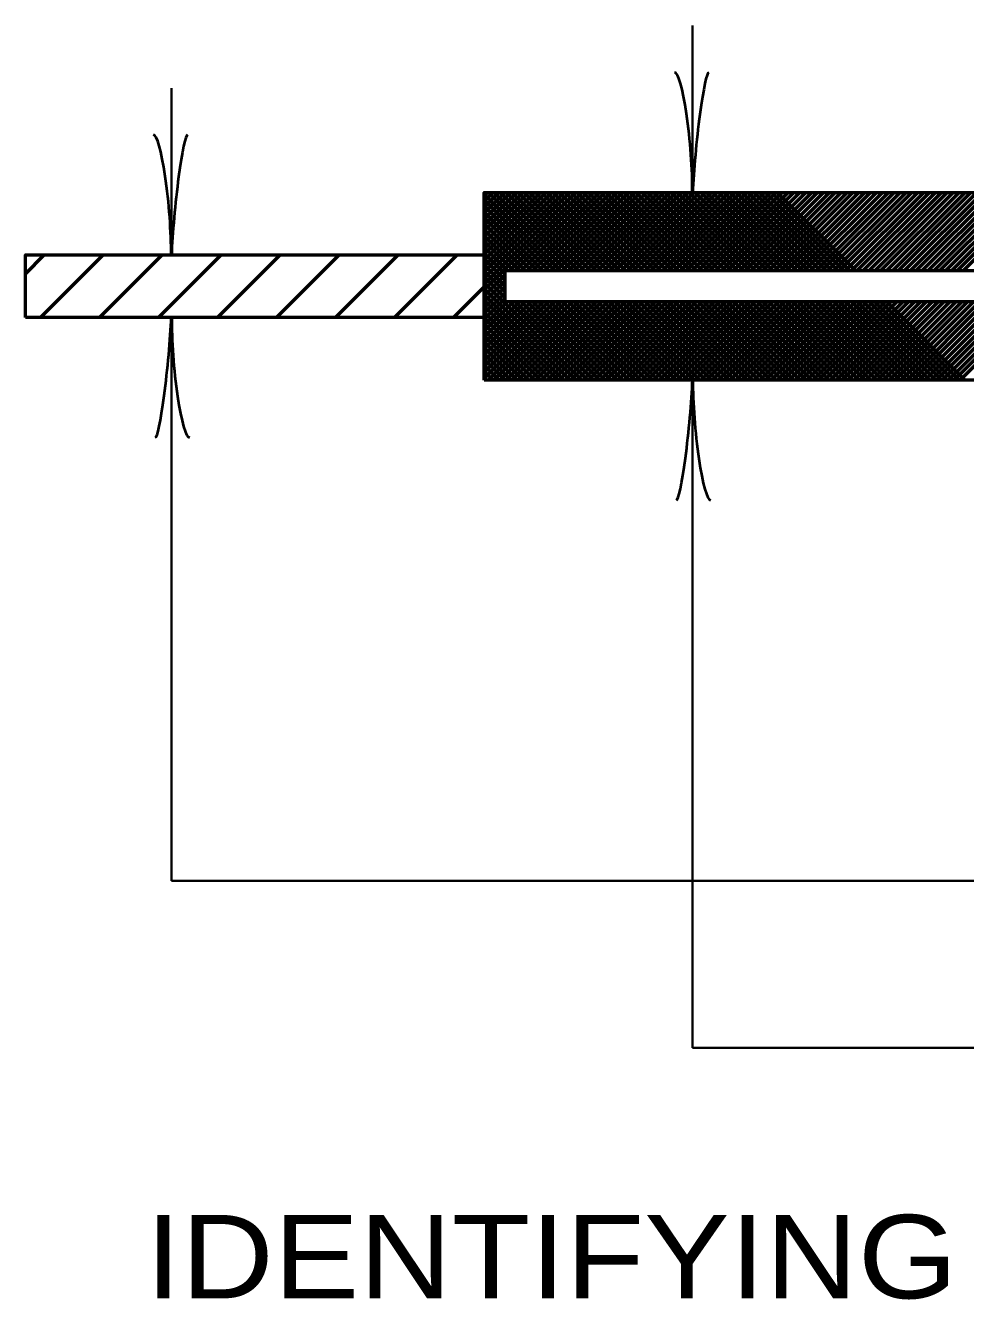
# Model space of a CAD drawing. Extents: x -32 to 824, y -6 to 538.
# Drawn here: x 339.48 to 366.53, y 145.51 to 182.16 of the extents above; entities that cross this region are included whole.
import ezdxf

# ---------------------------------------------------------------- set-up
doc = ezdxf.new("R2010")
doc.units = 0
doc.header["$LTSCALE"] = 1.1
doc.layers.add('1', color=7, linetype='Continuous', lineweight=53)

msp = doc.modelspace()

# ---------------------------------------------------------------- linework, layer by layer
at = {"layer": '1', "lineweight": 35}
for p, q in [((358.679, 177.362), (358.679, 182.162)), ((343.679, 175.562), (343.679, 180.362)), ((343.679, 173.762), (343.679, 157.562)), ((358.679, 171.962), (358.679, 152.752)), ((343.679, 157.562), (407.879, 157.562)), ((358.679, 152.752), (394.762, 152.752))]:
    msp.add_line(p, q, dxfattribs=at)
at = {"layer": '1'}
for p, q in [((352.679, 171.962), (352.679, 177.362)), ((352.679, 177.27), (352.771, 177.362)), ((352.679, 177.1), (352.94, 177.362)), ((352.679, 176.93), (353.11, 177.362)), ((352.679, 176.761), (353.28, 177.362)), ((352.679, 176.591), (353.45, 177.362)), ((352.679, 176.421), (353.619, 177.362)), ((352.679, 176.252), (353.789, 177.362)), ((352.679, 176.082), (353.959, 177.362)), ((352.679, 175.912), (354.128, 177.362)), ((352.679, 175.742), (354.298, 177.362)), ((352.679, 175.573), (354.468, 177.362)), ((352.679, 175.403), (354.637, 177.362)), ((352.679, 175.233), (354.807, 177.362)), ((352.679, 175.064), (354.977, 177.362)), ((352.679, 174.894), (355.147, 177.362)), ((352.679, 174.724), (355.316, 177.362)), ((352.679, 174.555), (355.486, 177.362)), ((354.88, 175.112), (352.679, 177.313)), ((354.711, 175.112), (352.679, 177.143)), ((355.05, 175.112), (352.8, 177.362)), ((355.22, 175.112), (352.97, 177.362)), ((355.389, 175.112), (353.139, 177.362)), ((355.559, 175.112), (353.309, 177.362)), ((353.406, 175.112), (355.656, 177.362)), ((355.729, 175.112), (353.479, 177.362)), ((353.575, 175.112), (355.825, 177.362)), ((355.899, 175.112), (353.649, 177.362)), ((353.745, 175.112), (355.995, 177.362)), ((356.068, 175.112), (353.818, 177.362)), ((353.915, 175.112), (356.165, 177.362)), ((356.238, 175.112), (353.988, 177.362)), ((354.084, 175.112), (356.334, 177.362)), ((356.408, 175.112), (354.158, 177.362)), ((354.254, 175.112), (356.504, 177.362)), ((356.577, 175.112), (354.327, 177.362)), ((354.424, 175.112), (356.674, 177.362)), ((356.747, 175.112), (354.497, 177.362)), ((354.594, 175.112), (356.844, 177.362)), ((356.917, 175.112), (354.667, 177.362)), ((354.763, 175.112), (357.013, 177.362)), ((357.087, 175.112), (354.837, 177.362)), ((354.933, 175.112), (357.183, 177.362)), ((357.256, 175.112), (355.006, 177.362)), ((355.103, 175.112), (357.353, 177.362)), ((357.426, 175.112), (355.176, 177.362)), ((355.273, 175.112), (357.523, 177.362)), ((357.596, 175.112), (355.346, 177.362)), ((355.442, 175.112), (357.692, 177.362)), ((357.765, 175.112), (355.515, 177.362)), ((355.612, 175.112), (357.862, 177.362)), ((357.935, 175.112), (355.685, 177.362)), ((355.782, 175.112), (358.032, 177.362)), ((358.105, 175.112), (355.855, 177.362)), ((355.951, 175.112), (358.201, 177.362)), ((358.274, 175.112), (356.024, 177.362)), ((356.121, 175.112), (358.371, 177.362)), ((358.444, 175.112), (356.194, 177.362)), ((356.291, 175.112), (358.541, 177.362)), ((358.614, 175.112), (356.364, 177.362)), ((356.46, 175.112), (358.71, 177.362)), ((358.784, 175.112), (356.534, 177.362)), ((356.63, 175.112), (358.88, 177.362)), ((358.953, 175.112), (356.703, 177.362)), ((356.8, 175.112), (359.05, 177.362)), ((359.123, 175.112), (356.873, 177.362)), ((356.97, 175.112), (359.22, 177.362)), ((359.293, 175.112), (357.043, 177.362)), ((357.139, 175.112), (359.389, 177.362)), ((359.462, 175.112), (357.212, 177.362)), ((357.309, 175.112), (359.559, 177.362)), ((359.632, 175.112), (357.382, 177.362)), ((357.479, 175.112), (359.729, 177.362)), ((359.802, 175.112), (357.552, 177.362)), ((357.648, 175.112), (359.898, 177.362)), ((359.971, 175.112), (357.721, 177.362)), ((357.818, 175.112), (360.068, 177.362)), ((360.141, 175.112), (357.891, 177.362)), ((357.988, 175.112), (360.238, 177.362)), ((360.311, 175.112), (358.061, 177.362)), ((358.158, 175.112), (360.408, 177.362)), ((360.481, 175.112), (358.231, 177.362)), ((358.327, 175.112), (360.577, 177.362)), ((360.65, 175.112), (358.4, 177.362)), ((358.497, 175.112), (360.747, 177.362)), ((360.82, 175.112), (358.57, 177.362)), ((358.667, 175.112), (360.917, 177.362)), ((360.99, 175.112), (358.74, 177.362)), ((358.836, 175.112), (361.086, 177.362)), ((361.16, 175.112), (358.91, 177.362)), ((359.006, 175.112), (361.256, 177.362)), ((361.329, 175.112), (359.079, 177.362)), ((359.176, 175.112), (361.426, 177.362)), ((361.499, 175.112), (359.249, 177.362)), ((359.345, 175.112), (361.595, 177.362)), ((361.669, 175.112), (359.419, 177.362)), ((359.515, 175.112), (361.765, 177.362)), ((361.838, 175.112), (359.588, 177.362)), ((359.685, 175.112), (361.935, 177.362)), ((362.008, 175.112), (359.758, 177.362)), ((359.855, 175.112), (362.105, 177.362)), ((362.178, 175.112), (359.928, 177.362)), ((360.024, 175.112), (362.274, 177.362)), ((362.347, 175.112), (360.097, 177.362)), ((360.194, 175.112), (362.444, 177.362)), ((362.517, 175.112), (360.267, 177.362)), ((360.364, 175.112), (362.614, 177.362)), ((362.687, 175.112), (360.437, 177.362)), ((360.533, 175.112), (362.783, 177.362)), ((362.857, 175.112), (360.607, 177.362)), ((360.703, 175.112), (362.953, 177.362)), ((363.026, 175.112), (360.776, 177.362)), ((360.873, 175.112), (363.123, 177.362)), ((363.196, 175.112), (360.946, 177.362)), ((361.042, 175.112), (363.292, 177.362)), ((363.366, 175.112), (361.116, 177.362)), ((361.212, 175.112), (363.462, 177.362)), ((361.382, 175.112), (363.632, 177.362)), ((361.552, 175.112), (363.802, 177.362)), ((361.721, 175.112), (363.971, 177.362)), ((361.891, 175.112), (364.141, 177.362)), ((362.061, 175.112), (364.311, 177.362)), ((362.23, 175.112), (364.48, 177.362)), ((362.4, 175.112), (364.65, 177.362)), ((362.57, 175.112), (364.82, 177.362)), ((362.74, 175.112), (364.99, 177.362)), ((362.909, 175.112), (365.159, 177.362)), ((363.079, 175.112), (365.329, 177.362)), ((363.249, 175.112), (365.499, 177.362)), ((363.418, 175.112), (365.668, 177.362)), ((363.588, 175.112), (365.838, 177.362)), ((363.758, 175.112), (366.008, 177.362)), ((363.927, 175.112), (366.177, 177.362)), ((364.097, 175.112), (366.347, 177.362)), ((364.267, 175.112), (366.517, 177.362)), ((364.437, 175.112), (366.687, 177.362)), ((364.606, 175.112), (366.856, 177.362)), ((364.776, 175.112), (367.026, 177.362)), ((364.946, 175.112), (367.196, 177.362)), ((365.115, 175.112), (367.365, 177.362)), ((365.285, 175.112), (367.535, 177.362)), ((365.455, 175.112), (367.705, 177.362)), ((365.625, 175.112), (367.875, 177.362)), ((365.794, 175.112), (368.044, 177.362)), ((365.964, 175.112), (368.214, 177.362)), ((366.134, 175.112), (368.384, 177.362)), ((366.303, 175.112), (368.553, 177.362)), ((366.473, 175.112), (368.723, 177.362)), ((354.541, 175.112), (352.679, 176.974)), ((354.371, 175.112), (352.679, 176.804)), ((354.202, 175.112), (352.679, 176.634)), ((354.032, 175.112), (352.679, 176.465)), ((353.862, 175.112), (352.679, 176.295)), ((353.692, 175.112), (352.679, 176.125)), ((353.523, 175.112), (352.679, 175.955)), ((339.479, 175.022), (340.018, 175.562)), ((339.915, 173.762), (341.715, 175.562)), ((341.612, 173.762), (343.412, 175.562)), ((343.309, 173.762), (345.109, 175.562)), ((345.006, 173.762), (346.806, 175.562)), ((346.703, 173.762), (348.503, 175.562)), ((348.401, 173.762), (350.201, 175.562)), ((350.098, 173.762), (351.898, 175.562)), ((353.353, 175.112), (352.679, 175.786)), ((353.279, 175.016), (352.679, 175.616)), ((353.279, 174.846), (352.679, 175.446)), ((353.279, 174.677), (352.679, 175.277)), ((353.279, 174.507), (352.679, 175.107)), ((352.679, 174.385), (353.279, 174.985)), ((353.279, 174.337), (352.679, 174.937)), ((352.679, 174.215), (353.279, 174.815)), ((351.795, 173.762), (352.679, 174.646)), ((355.485, 171.962), (352.679, 174.768)), ((352.679, 174.045), (353.279, 174.645)), ((355.315, 171.962), (352.679, 174.598)), ((352.679, 173.876), (353.279, 174.476)), ((355.145, 171.962), (352.679, 174.428)), ((352.679, 173.706), (353.279, 174.306)), ((354.976, 171.962), (352.679, 174.258)), ((352.679, 173.536), (353.354, 174.212)), ((352.679, 173.367), (353.524, 174.212)), ((352.679, 173.197), (353.694, 174.212)), ((352.679, 173.027), (353.863, 174.212)), ((352.679, 172.858), (354.033, 174.212)), ((352.679, 172.688), (354.203, 174.212)), ((352.679, 172.518), (354.373, 174.212)), ((352.679, 172.348), (354.542, 174.212)), ((352.679, 172.179), (354.712, 174.212)), ((352.679, 172.009), (354.882, 174.212)), ((354.806, 171.962), (352.679, 174.089)), ((352.801, 171.962), (355.051, 174.212)), ((352.971, 171.962), (355.221, 174.212)), ((353.141, 171.962), (355.391, 174.212)), ((353.31, 171.962), (355.56, 174.212)), ((355.655, 171.962), (353.405, 174.212)), ((353.48, 171.962), (355.73, 174.212)), ((355.824, 171.962), (353.574, 174.212)), ((353.65, 171.962), (355.9, 174.212)), ((355.994, 171.962), (353.744, 174.212)), ((353.82, 171.962), (356.07, 174.212)), ((356.164, 171.962), (353.914, 174.212)), ((353.989, 171.962), (356.239, 174.212)), ((356.333, 171.962), (354.083, 174.212)), ((354.159, 171.962), (356.409, 174.212)), ((356.503, 171.962), (354.253, 174.212)), ((354.329, 171.962), (356.579, 174.212)), ((356.673, 171.962), (354.423, 174.212)), ((354.498, 171.962), (356.748, 174.212)), ((356.842, 171.962), (354.592, 174.212)), ((354.668, 171.962), (356.918, 174.212)), ((357.012, 171.962), (354.762, 174.212)), ((354.838, 171.962), (357.088, 174.212)), ((357.182, 171.962), (354.932, 174.212)), ((355.007, 171.962), (357.257, 174.212)), ((357.352, 171.962), (355.102, 174.212)), ((355.177, 171.962), (357.427, 174.212)), ((357.521, 171.962), (355.271, 174.212)), ((355.347, 171.962), (357.597, 174.212)), ((357.691, 171.962), (355.441, 174.212)), ((355.517, 171.962), (357.767, 174.212)), ((357.861, 171.962), (355.611, 174.212)), ((355.686, 171.962), (357.936, 174.212)), ((358.03, 171.962), (355.78, 174.212)), ((355.856, 171.962), (358.106, 174.212)), ((358.2, 171.962), (355.95, 174.212)), ((356.026, 171.962), (358.276, 174.212)), ((358.37, 171.962), (356.12, 174.212)), ((356.195, 171.962), (358.445, 174.212)), ((358.54, 171.962), (356.29, 174.212)), ((356.365, 171.962), (358.615, 174.212)), ((358.709, 171.962), (356.459, 174.212)), ((356.535, 171.962), (358.785, 174.212)), ((358.879, 171.962), (356.629, 174.212)), ((356.704, 171.962), (358.954, 174.212)), ((359.049, 171.962), (356.799, 174.212)), ((356.874, 171.962), (359.124, 174.212)), ((359.218, 171.962), (356.968, 174.212)), ((357.044, 171.962), (359.294, 174.212)), ((359.388, 171.962), (357.138, 174.212)), ((357.214, 171.962), (359.464, 174.212)), ((359.558, 171.962), (357.308, 174.212)), ((357.383, 171.962), (359.633, 174.212)), ((359.727, 171.962), (357.477, 174.212)), ((357.553, 171.962), (359.803, 174.212)), ((359.897, 171.962), (357.647, 174.212)), ((357.723, 171.962), (359.973, 174.212)), ((360.067, 171.962), (357.817, 174.212)), ((357.892, 171.962), (360.142, 174.212)), ((360.237, 171.962), (357.987, 174.212)), ((358.062, 171.962), (360.312, 174.212)), ((360.406, 171.962), (358.156, 174.212)), ((358.232, 171.962), (360.482, 174.212)), ((360.576, 171.962), (358.326, 174.212)), ((358.402, 171.962), (360.652, 174.212)), ((360.746, 171.962), (358.496, 174.212)), ((358.571, 171.962), (360.821, 174.212)), ((360.915, 171.962), (358.665, 174.212)), ((358.741, 171.962), (360.991, 174.212)), ((361.085, 171.962), (358.835, 174.212)), ((358.911, 171.962), (361.161, 174.212)), ((361.255, 171.962), (359.005, 174.212)), ((359.08, 171.962), (361.33, 174.212)), ((361.425, 171.962), (359.175, 174.212)), ((359.25, 171.962), (361.5, 174.212)), ((361.594, 171.962), (359.344, 174.212)), ((359.42, 171.962), (361.67, 174.212)), ((361.764, 171.962), (359.514, 174.212)), ((359.59, 171.962), (361.84, 174.212)), ((361.934, 171.962), (359.684, 174.212)), ((359.759, 171.962), (362.009, 174.212)), ((362.103, 171.962), (359.853, 174.212)), ((359.929, 171.962), (362.179, 174.212)), ((362.273, 171.962), (360.023, 174.212)), ((360.099, 171.962), (362.349, 174.212)), ((362.443, 171.962), (360.193, 174.212)), ((360.268, 171.962), (362.518, 174.212)), ((362.612, 171.962), (360.362, 174.212)), ((360.438, 171.962), (362.688, 174.212)), ((362.782, 171.962), (360.532, 174.212)), ((360.608, 171.962), (362.858, 174.212)), ((362.952, 171.962), (360.702, 174.212)), ((360.777, 171.962), (363.027, 174.212)), ((363.122, 171.962), (360.872, 174.212)), ((360.947, 171.962), (363.197, 174.212)), ((363.291, 171.962), (361.041, 174.212)), ((361.117, 171.962), (363.367, 174.212)), ((363.461, 171.962), (361.211, 174.212)), ((361.287, 171.962), (363.537, 174.212)), ((363.631, 171.962), (361.381, 174.212)), ((361.456, 171.962), (363.706, 174.212)), ((363.8, 171.962), (361.55, 174.212)), ((361.626, 171.962), (363.876, 174.212)), ((363.97, 171.962), (361.72, 174.212)), ((361.796, 171.962), (364.046, 174.212)), ((364.14, 171.962), (361.89, 174.212)), ((361.965, 171.962), (364.215, 174.212)), ((364.31, 171.962), (362.06, 174.212)), ((362.135, 171.962), (364.385, 174.212)), ((364.479, 171.962), (362.229, 174.212)), ((362.305, 171.962), (364.555, 174.212)), ((364.649, 171.962), (362.399, 174.212)), ((362.475, 171.962), (364.725, 174.212)), ((364.819, 171.962), (362.569, 174.212)), ((362.644, 171.962), (364.894, 174.212)), ((364.988, 171.962), (362.738, 174.212)), ((362.814, 171.962), (365.064, 174.212)), ((365.158, 171.962), (362.908, 174.212)), ((362.984, 171.962), (365.234, 174.212)), ((365.328, 171.962), (363.078, 174.212)), ((363.153, 171.962), (365.403, 174.212)), ((365.497, 171.962), (363.247, 174.212)), ((363.323, 171.962), (365.573, 174.212)), ((365.667, 171.962), (363.417, 174.212)), ((363.493, 171.962), (365.743, 174.212)), ((365.837, 171.962), (363.587, 174.212)), ((363.662, 171.962), (365.912, 174.212)), ((366.007, 171.962), (363.757, 174.212)), ((363.832, 171.962), (366.082, 174.212)), ((366.176, 171.962), (363.926, 174.212)), ((364.002, 171.962), (366.252, 174.212)), ((366.346, 171.962), (364.096, 174.212)), ((364.172, 171.962), (366.422, 174.212)), ((366.516, 171.962), (364.266, 174.212)), ((364.341, 171.962), (366.591, 174.212)), ((364.511, 171.962), (366.761, 174.212)), ((364.681, 171.962), (366.931, 174.212)), ((364.85, 171.962), (367.1, 174.212)), ((365.02, 171.962), (367.27, 174.212)), ((365.19, 171.962), (367.44, 174.212)), ((365.36, 171.962), (367.61, 174.212)), ((365.529, 171.962), (367.779, 174.212)), ((365.699, 171.962), (367.949, 174.212)), ((365.869, 171.962), (368.119, 174.212)), ((366.038, 171.962), (368.288, 174.212)), ((366.208, 171.962), (368.458, 174.212)), ((366.378, 171.962), (368.628, 174.212)), ((352.679, 173.762), (339.479, 173.762)), ((354.636, 171.962), (352.679, 173.919)), ((354.466, 171.962), (352.679, 173.749)), ((354.297, 171.962), (352.679, 173.579)), ((354.127, 171.962), (352.679, 173.41)), ((353.957, 171.962), (352.679, 173.24)), ((353.788, 171.962), (352.679, 173.07)), ((353.618, 171.962), (352.679, 172.901)), ((353.448, 171.962), (352.679, 172.731)), ((353.279, 171.962), (352.679, 172.561)), ((353.109, 171.962), (352.679, 172.392)), ((352.939, 171.962), (352.679, 172.222)), ((352.769, 171.962), (352.679, 172.052))]:
    msp.add_line(p, q, dxfattribs=at)
for points in [[(352.679, 171.962), (352.679, 177.362), (382.079, 177.362), (382.679, 178.562), (395.279, 178.562), (396.479, 176.462), (395.879, 176.462), (395.879, 176.762), (394.679, 176.762), (394.679, 177.362), (382.679, 177.362), (382.679, 171.962), (394.679, 171.962), (394.679, 172.562), (395.879, 172.562), (395.879, 172.862), (396.479, 172.862), (395.279, 170.762), (382.679, 170.762), (382.079, 171.962)], [(352.679, 171.962), (352.679, 177.362), (382.079, 177.362), (382.679, 178.562), (395.279, 178.562), (396.479, 176.462), (395.879, 176.462), (395.879, 176.762), (394.679, 176.762), (394.679, 177.362), (382.679, 177.362), (382.679, 171.962), (394.679, 171.962), (394.679, 172.562), (395.879, 172.562), (395.879, 172.862), (396.479, 172.862), (395.279, 170.762), (382.679, 170.762), (382.079, 171.962)], [(382.079, 174.212), (353.279, 174.212), (353.279, 175.112), (382.079, 175.112)], [(353.279, 175.112), (382.079, 175.112), (382.079, 174.212), (353.279, 174.212)], [(353.279, 174.212), (353.279, 175.112), (382.079, 175.112), (382.079, 174.212)]]:
    msp.add_lwpolyline(points, close=True, dxfattribs=at)
for points in [[(358.679, 177.362), (382.079, 177.362), (382.679, 178.562), (395.279, 178.562), (396.479, 176.462), (395.879, 176.462), (395.879, 176.762), (394.679, 176.762), (394.679, 177.362), (382.679, 177.362), (382.679, 171.962), (394.679, 171.962), (394.679, 172.562), (395.879, 172.562), (395.879, 172.862), (396.479, 172.862), (395.279, 170.762), (382.679, 170.762), (382.079, 171.962), (352.679, 171.962)], [(339.479, 173.762), (339.479, 175.562), (352.679, 175.562)]]:
    msp.add_lwpolyline(points, dxfattribs=at)
at = {"layer": '1', "lineweight": 40}
for centre, major_axis, ratio, start_param, end_param in [((358.347, 178.671), (0.187, -2.143), 0.122415, 0.896353, 3.141593), ((358.933, 178.706), (-0.211, -2.108), 0.07063, 3.140715, 5.41811), ((343.347, 176.871), (0.187, -2.143), 0.122415, 0.896353, 3.141593), ((343.933, 176.906), (-0.211, -2.108), 0.07063, 3.140715, 5.41811), ((343.425, 172.417), (0.211, 2.108), 0.07063, 3.140715, 5.41811), ((343.425, 172.417), (0.211, 2.108), 0.07063, 3.140715, 5.41811), ((344.01, 172.452), (-0.187, 2.143), 0.122415, 0.896353, 3.141593), ((344.01, 172.452), (-0.187, 2.143), 0.122415, 0.896353, 3.141593), ((358.425, 170.617), (0.211, 2.108), 0.07063, 3.140715, 5.41811), ((358.425, 170.617), (0.211, 2.108), 0.07063, 3.140715, 5.41811), ((359.01, 170.652), (-0.187, 2.143), 0.122415, 0.896353, 3.141593), ((359.01, 170.652), (-0.187, 2.143), 0.122415, 0.896353, 3.141593)]:
    msp.add_ellipse(centre, major_axis=major_axis, ratio=ratio, start_param=start_param, end_param=end_param, dxfattribs=at)

# ---------------------------------------------------------------- texts
at = {"layer": '1', "width": 1.15}
msp.add_text('IDENTIFYING SYMBOLS V', height=2.4, dxfattribs=at).set_placement((342.931, 145.549))

doc.saveas('drawing.dxf')
